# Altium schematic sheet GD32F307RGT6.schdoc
size 127 x 101 mm
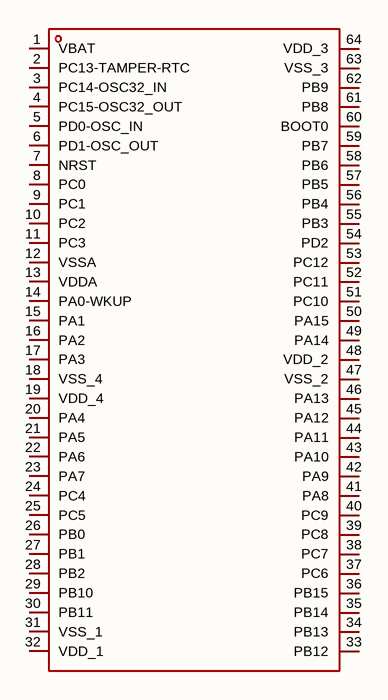
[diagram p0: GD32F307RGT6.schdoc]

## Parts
U?  gd32f307rgt6  [LQFP-64_L10.0-W10.0-P0.50-LS12.0-BL]  (value not drawn)

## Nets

Not connected (* = marked no-connect by the designer): U? 1(VBAT) 2(PC13-TAMPER-RTC) 3(PC14-OSC32_IN) 4(PC15-OSC32_OUT) 5(PD0-OSC_IN) 6(PD1-OSC_OUT) 7(NRST) 8(PC0) 9(PC1) 10(PC2) 11(PC3) 12(VSSA) 13(VDDA) 14(PA0-WKUP) 15(PA1) 16(PA2) 17(PA3) 18(VSS_4) 19(VDD_4) 20(PA4) 21(PA5) 22(PA6) 23(PA7) 24(PC4) 25(PC5) 26(PB0) 27(PB1) 28(PB2) 29(PB10) 30(PB11) 31(VSS_1) 32(VDD_1) 33(PB12) 34(PB13) 35(PB14) 36(PB15) 37(PC6) 38(PC7) 39(PC8) 40(PC9) 41(PA8) 42(PA9) 43(PA10) 44(PA11) 45(PA12) 46(PA13) 47(VSS_2) 48(VDD_2) 49(PA14) 50(PA15) 51(PC10) 52(PC11) 53(PC12) 54(PD2) 55(PB3) 56(PB4) 57(PB5) 58(PB6) 59(PB7) 60(BOOT0) 61(PB8) 62(PB9) 63(VSS_3) 64(VDD_3)

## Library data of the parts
U? = gd32f307rgt6: CPU内核:ARM Cortex-M4;CPU最大主频:120MHz;CPU位数:32 Bit;; Manufacturer: GigaDevice(兆易创新); AddInBom: yes; ModelId: cd9de06618c44fcf82654c43a457f83c; ModelName: LQFP-64_L10.0-W10.0-H1.4-LS12.0-P0.50; ModelTransform: 472.441,472.441,0,0,0,0,0,0.465,0; CPU Maximum Speed: 120MHz; Core Size: 32 Bit; Program Storage Size: 256KB; Program Memory Type: FLASH; Number of I/O: 51; ADC (Bit): 12bit; Oscillator Type: 内置+外置; Voltage - Supply: 2.6V~3.6V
